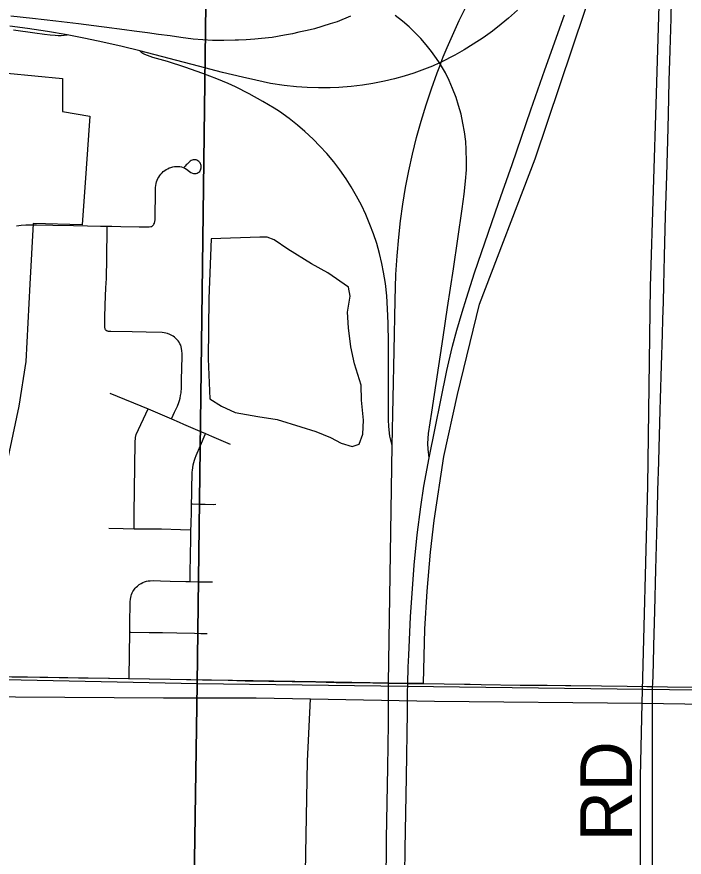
# Model space of a CAD drawing. Extents: x 0 to 34, y 0 to 22.
# Drawn here: x 3.211 to 3.943, y 14.756 to 15.678 of the extents above; entities that cross this region are included whole.
import ezdxf

# ---------------------------------------------------------------- set-up
doc = ezdxf.new("R2010")
doc.units = 0
for name, color, linetype in [('GM_X_City_Street', 7, 'Continuous'), ('GM_X_Corporation', 7, 'Continuous'), ('GM_X_County_Road', 7, 'Continuous'), ('GM_X_Interchange_Ramps', 7, 'Continuous'), ('GM_X_Interstate_Route', 7, 'Continuous'), ('GM_X_Minor_Lake', 7, 'Continuous'), ('GM_X_Minor_River', 7, 'Continuous'), ('GM_X_Township_Road', 7, 'Continuous'), ('GM_X_Township_Road_Text', 7, 'Continuous'), ('GM_X_US_Route', 7, 'Continuous')]:
    doc.layers.add(name, color=color, linetype=linetype)

msp = doc.modelspace()

# ---------------------------------------------------------------- linework, layer by layer
at = {"layer": 'GM_X_City_Street'}
for points in [[(3.21075, 15.44877), (3.21572, 15.44934), (3.22072, 15.44964), (3.22635, 15.44978), (3.23259, 15.44975), (3.25063, 15.4493), (3.273, 15.4489), (3.28854, 15.44855), (3.30284, 15.44847), (3.31019, 15.44828), (3.31527, 15.44814), (3.32521, 15.44793), (3.34537, 15.44771), (3.35443, 15.44761), (3.35623, 15.44763), (3.35797, 15.44782), (3.35895, 15.44808), (3.36021, 15.44893), (3.36091, 15.44973), (3.36147, 15.45066), (3.3619, 15.4517), (3.36235, 15.45338), (3.3626, 15.45513), (3.36271, 15.45755), (3.36289, 15.4668), (3.36309, 15.47681), (3.36303, 15.48676), (3.3632, 15.49055), (3.36345, 15.49308), (3.36378, 15.49499), (3.36427, 15.49687), (3.36494, 15.4987), (3.36576, 15.50046), (3.36671, 15.50216), (3.36777, 15.50377), (3.36896, 15.5053), (3.37026, 15.50674), (3.37167, 15.50808), (3.37318, 15.50929), (3.37479, 15.51038), (3.37648, 15.51133), (3.37825, 15.51215), (3.38008, 15.5128), (3.38196, 15.51331), (3.38387, 15.51366), (3.38582, 15.51384), (3.38777, 15.51382), (3.38972, 15.51363), (3.39165, 15.51325), (3.39353, 15.51262), (3.39531, 15.51176), (3.39696, 15.51072), (3.40048, 15.50814), (3.40198, 15.50721), (3.40354, 15.5065), (3.40463, 15.5062), (3.40572, 15.50604), (3.40683, 15.50604), (3.40791, 15.50621), (3.40897, 15.50652), (3.40994, 15.50699), (3.41082, 15.50762), (3.41158, 15.50839), (3.4122, 15.50929), (3.41268, 15.51028), (3.41302, 15.51134), (3.41322, 15.51245), (3.41328, 15.51357), (3.41319, 15.51467), (3.41294, 15.51576), (3.41253, 15.51678), (3.41198, 15.51774), (3.4113, 15.51861), (3.4105, 15.51938), (3.4096, 15.52003), (3.40862, 15.52054), (3.40757, 15.5209), (3.40649, 15.52111), (3.40538, 15.52116), (3.40429, 15.52104), (3.40323, 15.52076), (3.40222, 15.52032), (3.40126, 15.51973), (3.4004, 15.51903), (3.39892, 15.51758), (3.3978, 15.51645), (3.39685, 15.51547), (3.39562, 15.51421), (3.39442, 15.513)], [(3.30892, 15.33368), (3.30826, 15.33463), (3.30793, 15.33532), (3.30773, 15.33598), (3.30761, 15.33672), (3.30761, 15.338), (3.30755, 15.3394), (3.30761, 15.34367), (3.30766, 15.34781), (3.30803, 15.36215), (3.30875, 15.38083), (3.30921, 15.39077), (3.30969, 15.41319), (3.31016, 15.44585), (3.31019, 15.44828)], [(3.38074, 15.23711), (3.38108, 15.23784), (3.38406, 15.24412), (3.38547, 15.24711), (3.38716, 15.25068), (3.38874, 15.25473), (3.38951, 15.25709), (3.39014, 15.2595), (3.39071, 15.26254), (3.3911, 15.26562), (3.39147, 15.2712), (3.39179, 15.27865), (3.39198, 15.29357), (3.39229, 15.30413), (3.39232, 15.30848), (3.39214, 15.31158), (3.39177, 15.31404), (3.39133, 15.31585), (3.39073, 15.31761), (3.38994, 15.3193), (3.38899, 15.32091), (3.3879, 15.32242), (3.3867, 15.32385), (3.3854, 15.32518), (3.384, 15.32641), (3.38251, 15.32752), (3.38092, 15.32851), (3.3787, 15.32964), (3.37638, 15.33054), (3.3746, 15.33105), (3.37277, 15.3314), (3.3703, 15.33163), (3.3529, 15.33207), (3.33736, 15.33228), (3.31416, 15.3329), (3.31172, 15.3329), (3.31077, 15.33298), (3.30991, 15.33315), (3.30892, 15.33368)], [(3.31284, 15.26524), (3.35495, 15.2478), (3.38074, 15.23711), (3.38914, 15.23328), (3.39366, 15.2312), (3.40911, 15.22463), (3.41809, 15.22074), (3.42451, 15.21795), (3.44517, 15.20933)], [(3.33962, 15.11644), (3.33964, 15.11767), (3.33972, 15.12248), (3.3398, 15.1279), (3.33988, 15.13305), (3.3408, 15.21084), (3.34102, 15.21629), (3.34204, 15.21969), (3.35495, 15.2478)], [(3.40098, 15.0585), (3.401, 15.06019), (3.4011, 15.06967), (3.40151, 15.08522), (3.40184, 15.10699), (3.40202, 15.11532), (3.40213, 15.12066), (3.40251, 15.13621), (3.40266, 15.14354), (3.40287, 15.15363), (3.403, 15.16359), (3.40328, 15.17414), (3.4035, 15.17835), (3.40366, 15.18073), (3.40399, 15.18334), (3.40448, 15.18641), (3.40505, 15.18896), (3.40579, 15.19151), (3.40661, 15.1939), (3.40783, 15.19682), (3.41247, 15.20767), (3.41763, 15.21965), (3.41809, 15.22074)], [(3.40266, 15.14354), (3.4036, 15.14353), (3.41214, 15.14339), (3.41751, 15.1433), (3.42669, 15.14315), (3.42918, 15.14316)], [(3.31197, 15.11705), (3.32746, 15.11675), (3.33962, 15.11644), (3.34232, 15.11637), (3.35613, 15.11623), (3.36958, 15.1161), (3.39045, 15.1156), (3.40202, 15.11532)], [(3.33419, 14.95202), (3.33422, 14.95361), (3.3349, 15.00304), (3.33511, 15.01824), (3.33526, 15.02941), (3.33538, 15.03621), (3.33561, 15.03923), (3.33589, 15.04099), (3.33631, 15.04273), (3.33686, 15.04443), (3.33756, 15.04607), (3.33838, 15.04765), (3.33933, 15.04916), (3.34079, 15.05105), (3.342, 15.05236), (3.34332, 15.05357), (3.3452, 15.05504), (3.34723, 15.05634), (3.34934, 15.05745), (3.35099, 15.05812), (3.35327, 15.05879), (3.35502, 15.05914), (3.3574, 15.0594), (3.36045, 15.05947), (3.36861, 15.05927), (3.37904, 15.05904), (3.39641, 15.05864), (3.40098, 15.0585), (3.40944, 15.05826), (3.41628, 15.0581), (3.42562, 15.05814)], [(3.3349, 15.00304), (3.33618, 15.00302), (3.356, 15.00271), (3.37092, 15.0024), (3.38646, 15.00209), (3.40602, 15.00169), (3.41288, 15.00154), (3.41986, 15.0014)]]:
    msp.add_lwpolyline(points, dxfattribs=at)
at = {"layer": 'GM_X_Corporation'}
for points in [[(2.41416, 15.97585), (3.42156, 15.95047), (3.40873, 14.94631), (2.39105, 14.96729)], [(3.42156, 15.95047), (4.43539, 15.94772), (4.41668, 14.93339), (3.40873, 14.94631)], [(2.36635, 14.1), (3.39599, 14.1), (3.40873, 14.94631), (2.39105, 14.96729)], [(3.39599, 14.1), (4.40156, 14.1), (4.41668, 14.93339), (3.40873, 14.94631)]]:
    msp.add_lwpolyline(points, close=True, dxfattribs=at)
msp.add_lwpolyline([(3.15616, 14.955), (3.33366, 14.95213), (3.53875, 14.94883), (3.61861, 14.94742), (3.64253, 14.94702), (3.65722, 14.94707), (3.65869, 15.00621), (3.66102, 15.04787), (3.66474, 15.09065), (3.66869, 15.12529), (3.67943, 15.19546), (3.69451, 15.26363), (3.71875, 15.36259), (3.77955, 15.52201), (3.86157, 15.76592), (3.92242, 15.8956), (3.94042, 15.92161), (3.94197, 15.92452), (3.94414, 15.92812)], dxfattribs=at)
at = {"layer": 'GM_X_County_Road'}
for points in [[(3.13385, 14.9547), (3.14021, 14.95462), (3.15639, 14.95445), (3.1774, 14.95419), (3.20535, 14.95384), (3.2363, 14.95346), (3.27858, 14.95282), (3.31276, 14.9523), (3.33419, 14.95202)], [(3.33419, 14.95202), (3.37928, 14.95127), (3.41471, 14.95068), (3.44268, 14.9501), (3.46133, 14.94969), (3.53898, 14.94828), (3.56134, 14.94789), (3.58434, 14.94754), (3.61865, 14.94686), (3.63983, 14.94652), (3.64276, 14.94647), (3.65745, 14.94651)], [(3.65745, 14.94651), (3.70223, 14.94578), (3.70845, 14.94577), (3.72026, 14.94557), (3.76313, 14.94485), (3.77493, 14.94483), (3.79296, 14.94466), (3.81285, 14.94443), (3.81882, 14.94439)], [(3.81882, 14.94439), (3.85265, 14.94416), (3.88063, 14.94375), (3.90239, 14.94331), (3.90859, 14.94321)], [(3.90859, 14.94321), (3.92476, 14.94296), (3.96517, 14.94242), (3.99501, 14.94195), (4.03542, 14.94127), (4.08453, 14.94054), (4.11189, 14.94019), (4.14421, 14.93965), (4.1896, 14.9391), (4.23809, 14.93857), (4.26855, 14.93809), (4.32016, 14.93736), (4.34875, 14.93696), (4.38233, 14.93657), (4.40905, 14.9361), (4.45972, 14.93564)]]:
    msp.add_lwpolyline(points, dxfattribs=at)
at = {"layer": 'GM_X_Interchange_Ramps'}
msp.add_lwpolyline([(3.20716, 15.66349), (3.2307, 15.66048), (3.24144, 15.65904), (3.24765, 15.65823), (3.25309, 15.65777), (3.25649, 15.65732), (3.25964, 15.6575), (3.26618, 15.65808)], dxfattribs=at)
at = {"layer": 'GM_X_Interstate_Route'}
for points in [[(3.62279, 15.20786), (3.62489, 15.31136), (3.62601, 15.36729), (3.62697, 15.39523), (3.62822, 15.41569), (3.62998, 15.43611), (3.63195, 15.454), (3.63453, 15.47245), (3.63759, 15.49083), (3.64112, 15.50914), (3.64513, 15.52737), (3.6496, 15.54549), (3.65455, 15.56349), (3.65995, 15.58136), (3.66581, 15.59908), (3.67213, 15.61665), (3.67568, 15.6258), (3.67659, 15.62817), (3.67887, 15.63405), (3.68317, 15.64437), (3.68885, 15.65748), (3.69637, 15.67384), (3.70405, 15.68944)], [(3.66339, 15.19433), (3.6624, 15.20383), (3.66177, 15.20996), (3.66216, 15.21536), (3.66256, 15.22095), (3.66625, 15.24429), (3.67868, 15.32668), (3.68363, 15.35925), (3.69005, 15.40166), (3.69968, 15.46746), (3.70183, 15.48347), (3.70336, 15.49769), (3.70421, 15.5101), (3.70451, 15.5194), (3.70416, 15.53245), (3.70347, 15.54112), (3.70218, 15.5516), (3.70049, 15.56141), (3.69834, 15.57112), (3.69573, 15.58072), (3.69286, 15.5896), (3.68911, 15.59949), (3.68539, 15.60804), (3.68117, 15.61636), (3.67689, 15.62393), (3.67568, 15.6258), (3.6747, 15.62729), (3.67147, 15.63227), (3.66602, 15.63985), (3.6602, 15.64713), (3.65409, 15.65418), (3.64851, 15.66003), (3.6413, 15.66689), (3.63425, 15.67299), (3.62593, 15.67952)], [(3.66339, 15.19433), (3.68275, 15.29), (3.68498, 15.29941), (3.68906, 15.31664), (3.69385, 15.33404), (3.69945, 15.3538), (3.70419, 15.36928), (3.71325, 15.39709), (3.73203, 15.45247), (3.73944, 15.47361), (3.74417, 15.48711), (3.75429, 15.51585), (3.77503, 15.5758), (3.79038, 15.61986), (3.81171, 15.68027)], [(3.62279, 15.20786), (3.62015, 15.21786), (3.6191, 15.22838), (3.61869, 15.23576), (3.61866, 15.24252), (3.6186, 15.32026), (3.61833, 15.34203), (3.61779, 15.35757), (3.61682, 15.37184), (3.61534, 15.38544), (3.61344, 15.39773), (3.6115, 15.40749), (3.6089, 15.41838), (3.60583, 15.42915), (3.60236, 15.43979), (3.59841, 15.45026), (3.5938, 15.46114), (3.58899, 15.47126), (3.58379, 15.48117), (3.57787, 15.4914), (3.57218, 15.50031), (3.56541, 15.51), (3.55861, 15.51889), (3.55105, 15.52797), (3.54348, 15.53622), (3.53603, 15.54372), (3.52691, 15.55217), (3.51886, 15.55904), (3.50961, 15.56639), (3.49902, 15.57403), (3.4933, 15.57777), (3.48106, 15.58518), (3.46578, 15.59354), (3.45077, 15.60106), (3.44284, 15.60466), (3.43024, 15.60997), (3.41513, 15.61575), (3.39516, 15.6227), (3.3762, 15.62876), (3.36017, 15.63344), (3.35159, 15.63644), (3.35052, 15.63694), (3.34939, 15.63762), (3.34821, 15.63852), (3.34576, 15.64056), (3.32643, 15.64529), (3.30522, 15.65022), (3.28633, 15.65415), (3.26618, 15.65808), (3.24473, 15.66188), (3.22258, 15.66526), (3.2034, 15.66777)], [(3.61869, 14.93686), (3.61865, 14.94686), (3.62279, 15.20786)], [(3.64051, 14.96457), (3.641, 14.97761), (3.64283, 15.01957), (3.64692, 15.07653), (3.65022, 15.1096), (3.65429, 15.14028), (3.65757, 15.16311), (3.66339, 15.19433)], [(3.63974, 14.93639), (3.63983, 14.94652), (3.64051, 14.96457)], [(3.61486, 14.6691), (3.6164, 14.75862), (3.6167, 14.77665), (3.61813, 14.85436), (3.61884, 14.90286), (3.61869, 14.93686)], [(3.62682, 14.1), (3.62691, 14.10572), (3.62848, 14.20519), (3.62975, 14.28103), (3.63002, 14.29906), (3.63167, 14.4097), (3.63256, 14.46192), (3.6328, 14.4756), (3.63302, 14.49176), (3.63423, 14.56201), (3.63473, 14.59123), (3.6353, 14.63038), (3.63555, 14.65277), (3.63572, 14.6652), (3.63622, 14.70872), (3.6366, 14.7367), (3.63706, 14.7653), (3.63779, 14.80446), (3.63843, 14.84425), (3.63953, 14.91511), (3.63974, 14.93639)]]:
    msp.add_lwpolyline(points, dxfattribs=at)
at = {"layer": 'GM_X_Minor_Lake'}
for points in [[(3.47761, 15.4363), (3.42426, 15.43456), (3.42153, 15.36893), (3.42106, 15.30286), (3.42264, 15.25877), (3.43568, 15.25085), (3.45063, 15.24403), (3.47547, 15.23963)], [(3.47547, 15.23963), (3.49678, 15.23635), (3.52273, 15.22806), (3.53891, 15.22292), (3.55507, 15.21665), (3.5667, 15.21043), (3.57874, 15.20648), (3.58671, 15.20904), (3.59063, 15.22), (3.59121, 15.23555), (3.58922, 15.25759), (3.58868, 15.27391), (3.58143, 15.29716), (3.57752, 15.3158), (3.57477, 15.33671), (3.57386, 15.3538), (3.57673, 15.3716), (3.57497, 15.38149), (3.55213, 15.39695), (3.53413, 15.40705), (3.50827, 15.42293), (3.4933, 15.43337), (3.48551, 15.43606), (3.47761, 15.4363)]]:
    msp.add_lwpolyline(points, dxfattribs=at)
at = {"layer": 'GM_X_Minor_River'}
for points in [[(3.89287, 14.1), (3.89419, 14.22149), (3.89327, 14.3828), (3.89504, 14.43136), (3.89556, 14.64539), (3.89512, 14.84426), (3.89693, 14.92508), (3.90343, 15.16333), (3.90628, 15.38189), (3.91282, 15.59396), (3.91959, 15.82387), (3.92151, 15.91303)], [(3.20034, 15.61624), (3.26106, 15.61021), (3.26094, 15.57413), (3.29105, 15.56884), (3.28701, 15.51159), (3.28249, 15.4498), (3.22884, 15.4511), (3.22534, 15.38473), (3.22101, 15.29976), (3.21302, 15.25097), (3.19848, 15.18182)], [(3.155, 14.93223), (3.37195, 14.93074), (3.47353, 14.93076)], [(3.47353, 14.93076), (3.5332, 14.92963), (3.66917, 14.92717), (3.89693, 14.92508), (4.1073, 14.92169), (4.31316, 14.91987), (4.41854, 14.91893), (4.54507, 14.91696)], [(3.52434, 14.59729), (3.52771, 14.73956), (3.53005, 14.86136), (3.5332, 14.92963)]]:
    msp.add_lwpolyline(points, dxfattribs=at)
at = {"layer": 'GM_X_Township_Road'}
for points in [[(3.90859, 14.94321), (3.90864, 14.94556), (3.90939, 14.96858), (3.91002, 14.98783), (3.91104, 15.02632), (3.91225, 15.07175), (3.91405, 15.13764), (3.91446, 15.15816), (3.91541, 15.18987), (3.91585, 15.2054), (3.91621, 15.21846), (3.9169, 15.24643), (3.91722, 15.25886), (3.91831, 15.29554), (3.91924, 15.32973), (3.91984, 15.34589), (3.92049, 15.36515), (3.92095, 15.38317), (3.92167, 15.4155), (3.92285, 15.45965), (3.92415, 15.50378), (3.9252, 15.54231), (3.92596, 15.57091), (3.92686, 15.60759), (3.92787, 15.64116), (3.92883, 15.67596), (3.92967, 15.717)], [(3.90703, 14.1), (3.90712, 14.12533), (3.90717, 14.15766), (3.90714, 14.19249), (3.90723, 14.21239), (3.90738, 14.2783), (3.90748, 14.3125), (3.90755, 14.34173), (3.9077, 14.36909), (3.90738, 14.41946), (3.90759, 14.4605), (3.90779, 14.51709), (3.90786, 14.54321), (3.90793, 14.56622), (3.90793, 14.6284), (3.90802, 14.65079), (3.90811, 14.70116), (3.9084, 14.75775), (3.90844, 14.7963), (3.90837, 14.84916), (3.90857, 14.89518), (3.90858, 14.91507), (3.90852, 14.93934), (3.90859, 14.94321)]]:
    msp.add_lwpolyline(points, dxfattribs=at)
at = {"layer": 'GM_X_US_Route'}
for points in [[(3.76022, 15.68541), (3.75059, 15.67664), (3.74253, 15.66986), (3.73275, 15.66224), (3.72269, 15.65499), (3.71183, 15.6478), (3.70175, 15.64169), (3.69146, 15.63595), (3.67659, 15.62817), (3.6747, 15.62729), (3.66703, 15.62389), (3.65842, 15.6204), (3.64674, 15.61627), (3.63611, 15.61289), (3.62534, 15.60996), (3.61448, 15.6074), (3.6017, 15.60491), (3.59006, 15.60308), (3.57775, 15.6016), (3.56416, 15.60046), (3.55487, 15.60006), (3.54185, 15.59994), (3.52946, 15.60031), (3.51772, 15.60111), (3.50416, 15.60257), (3.48947, 15.60492), (3.47306, 15.60828), (3.45853, 15.61159), (3.43681, 15.6169), (3.41035, 15.6238), (3.34576, 15.64056)], [(3.57703, 15.67854), (3.56261, 15.67258), (3.55474, 15.67021), (3.53752, 15.66493), (3.52965, 15.66311), (3.52026, 15.66093), (3.51327, 15.6593), (3.50459, 15.65772), (3.4911, 15.65521), (3.47933, 15.65404), (3.47201, 15.65331), (3.46276, 15.65284), (3.4542, 15.65239), (3.45067, 15.65221), (3.4381, 15.65209), (3.42936, 15.65203), (3.42571, 15.65201), (3.4044, 15.65341), (3.39088, 15.65529), (3.37925, 15.65695), (3.3665, 15.65872), (3.35435, 15.66037), (3.33955, 15.66236), (3.32925, 15.66374), (3.30695, 15.66659), (3.30388, 15.667), (3.27876, 15.67011), (3.25361, 15.67314), (3.22831, 15.67603), (3.20439, 15.67882)]]:
    msp.add_lwpolyline(points, dxfattribs=at)

# ---------------------------------------------------------------- texts
at = {"layer": 'GM_X_Township_Road_Text'}
msp.add_text('RD', height=0.056818, rotation=90, dxfattribs=at).set_placement((3.88599, 14.77357))

doc.saveas('drawing.dxf')
